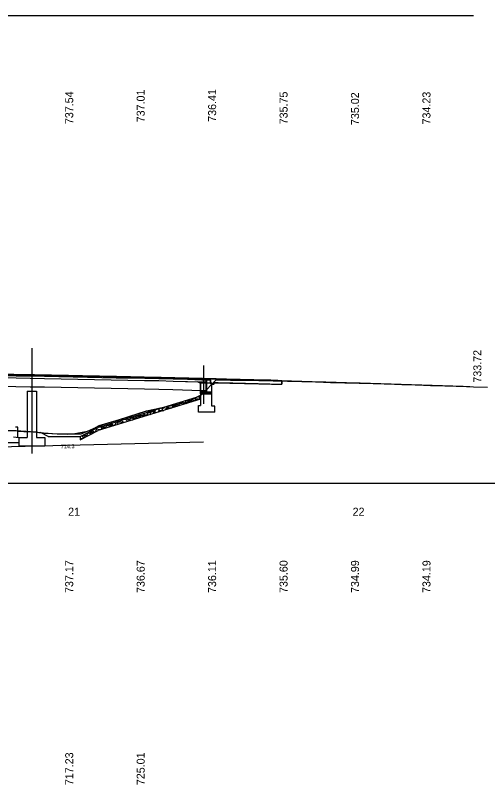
# Model space of a CAD drawing. Extents: x -434 to 1339, y -871 to 603.
# Drawn here: x 579.8 to 745, y -105.4 to 163.6 of the extents above; entities that cross this region are included whole.
import ezdxf

# ---------------------------------------------------------------- set-up
doc = ezdxf.new("R2010")
doc.units = 0
for name, color, linetype in [('BR_P_Brg_Pad_Object', 7, 'Continuous'), ('BR_P_Gen_Approach_Slab', 7, 'Continuous'), ('BR_P_Gen_Hatch', 7, 'Continuous'), ('BR_P_Gen_Slope_Protection', 7, 'Continuous'), ('BR_P_Slab_Object', 7, 'Continuous'), ('BR_P_Sub_Const_Joint', 7, 'Continuous'), ('BR_P_Sub_Object', 7, 'Continuous'), ('BR_X_Beam_Object', 7, 'Continuous'), ('BR_X_Gen_Approach_Slab', 7, 'Continuous'), ('BR_X_Sub_Centerline', 7, 'Continuous'), ('BR_X_Sub_Object', 7, 'Continuous'), ('Default', 7, 'Continuous'), ('GK_Cells', 7, 'Continuous'), ('PF_P_Grade_Line', 7, 'Continuous'), ('PF_P_Sta_Elev_Text', 7, 'Continuous'), ('PF_P_Text', 7, 'Continuous'), ('PF_X_Ground_Line', 7, 'Continuous'), ('SC_Scratch1', 7, 'Continuous'), ('SC_Scratch2', 7, 'Continuous'), ('XS_P_Annotation', 7, 'Continuous'), ('XS_P_Barrier_Surface', 7, 'Continuous'), ('XS_P_Ditch_Bottom', 7, 'Continuous'), ('XS_P_Finished_Grade', 7, 'Continuous'), ('XS_P_Finished_Grade_Seeded', 7, 'Continuous'), ('XS_P_Subgrade', 7, 'Continuous'), ('XS_X_Ground_Line', 7, 'Continuous')]:
    doc.layers.add(name, color=color, linetype=linetype)

msp = doc.modelspace()

# ---------------------------------------------------------------- linework, layer by layer
at = {"layer": 'BR_P_Brg_Pad_Object'}
msp.add_lwpolyline([(645.13, 31.83), (646.13, 31.83), (646.13, 31.66), (645.13, 31.66)], close=True, dxfattribs=at)
at = {"layer": 'BR_P_Gen_Approach_Slab'}
for p, q in [((649.03, 34.74), (649.46, 35.17)), ((673, 34.55), (673, 35.8)), ((649.03, 34.74), (648.53, 34.74))]:
    msp.add_line(p, q, dxfattribs=at)
msp.add_open_spline([(649.46, 35.17), (657.31, 34.97), (665.16, 34.77), (673, 34.55)], degree=2, dxfattribs=at)
at = {"layer": 'BR_P_Gen_Hatch'}
for p, q in [((643.57, 35.44), (644.57, 34.95)), ((649.03, 34.74), (649.46, 35.17)), ((673, 34.55), (673, 35.8)), ((644.57, 34.95), (644.57, 31.24)), ((648.53, 31.24), (648.53, 34.74)), ((648.53, 34.74), (649.03, 34.74)), ((644.57, 31.24), (648.53, 31.24))]:
    msp.add_line(p, q, dxfattribs=at)
for points in [[(355.72, 38.2), (400, 38.39), (405, 38.4), (410, 38.38), (450, 38.22), (454.99, 38.18), (494.99, 37.8), (499.99, 37.75), (534.99, 37.4), (539.99, 37.35), (579.99, 36.78), (584.99, 36.71), (589.99, 36.61), (624.99, 35.92), (629.98, 35.83), (634.98, 35.69), (643.57, 35.44)], [(642.45, 29.76), (642.47, 29.76), (642.76, 29.41), (642.72, 29.05), (642.39, 28.76), (642.1, 28.75), (641.81, 28.95)], [(643.27, 30.01), (642.95, 29.73), (642.66, 29.73), (642.57, 29.79)], [(644.45, 29.33), (644.27, 29.49), (644.17, 29.9), (644.21, 30.24)], [(644.21, 30.22), (644.25, 30.31)], [(634.3, 27.25), (634.38, 27.22), (634.69, 26.85), (634.7, 26.53), (634.42, 26.26), (633.86, 26.19), (633.29, 26.38), (632.92, 26.73), (632.91, 26.83)], [(636.05, 27.79), (636.05, 27.53), (635.77, 27.26), (635.21, 27.19), (634.67, 27.37)], [(635.02, 26.43), (634.99, 26.61), (635.28, 26.95), (635.73, 26.94), (635.92, 26.71)], [(636.06, 26.95), (636.01, 27.23), (636.19, 27.44), (636.46, 27.43), (636.63, 27.22), (636.61, 27.01), (636.45, 26.87)], [(636.32, 26.83), (636.23, 26.83), (636.06, 26.95)], [(637.39, 27.16), (637.14, 27.4), (637.08, 27.74), (637.34, 28.05), (637.76, 28.14), (638.1, 28.1)], [(638.07, 28.11), (638.59, 27.88), (638.83, 27.6)], [(638.5, 28.01), (638.42, 28.49), (638.45, 28.53)], [(639.21, 28.76), (639.45, 28.47), (639.42, 28.11), (639.08, 27.82), (638.8, 27.82), (638.5, 28.01)], [(639.42, 27.78), (639.52, 28.02), (639.89, 28.33), (640.21, 28.33), (640.44, 28.09)], [(640.19, 28.55), (640.14, 28.84), (640.32, 29.04), (640.59, 29.03), (640.76, 28.82), (640.74, 28.61), (640.54, 28.44), (640.36, 28.43), (640.19, 28.55)], [(640.61, 29.19), (640.6, 29.19), (640.59, 29.19)], [(640.75, 28.19), (640.71, 28.4), (641.01, 28.73), (641.46, 28.72), (641.67, 28.47)], [(641.81, 28.95), (641.72, 29.43), (641.85, 29.57)], [(643.06, 28.9), (643.02, 29.14), (643.32, 29.48), (643.77, 29.47), (644, 29.19)], [(624.67, 24.3), (624.55, 23.94), (624.2, 23.58), (623.85, 23.52), (623.55, 23.78), (623.51, 23.94)], [(625.05, 23.92), (624.97, 24.39)], [(625.79, 24.64), (626, 24.38), (625.97, 24.02), (625.63, 23.73), (625.34, 23.73), (625.05, 23.92)], [(627.23, 25.09), (627.24, 24.97), (626.96, 24.7), (626.4, 24.63), (626.09, 24.73)], [(626.86, 23.93), (626.9, 24.24)], [(626.89, 24.21), (627.11, 24.73), (627.48, 25.04), (627.8, 25.05), (628.07, 24.77), (628.13, 24.31)], [(627.94, 25.09), (627.91, 25.29)], [(628.44, 25.45), (628.51, 25.36), (628.49, 25.15), (628.29, 24.97), (628.12, 24.97), (627.94, 25.09)], [(628.86, 24.54), (628.73, 24.66), (628.64, 25.07), (628.68, 25.41)], [(628.67, 25.39), (628.74, 25.55)], [(629.86, 25.89), (629.92, 25.38), (629.73, 24.81), (629.72, 24.8)], [(630.18, 25.48), (630.1, 25.96), (630.11, 25.97)], [(630.9, 26.21), (631.13, 25.93), (631.1, 25.57), (630.76, 25.28), (630.47, 25.28), (630.18, 25.48)], [(631.08, 25.22), (631.17, 25.32), (631.58, 25.41), (631.67, 25.4)], [(632.06, 26.57), (632.04, 26.53), (631.69, 26.16), (631.35, 26.1), (631.14, 26.28)], [(632.5, 25.66), (632.45, 25.94), (632.75, 26.27), (633.19, 26.26), (633.45, 25.95)], [(617.96, 21.19), (617.89, 21.18), (617.33, 21.37), (616.96, 21.73), (616.93, 21.92)], [(618.19, 22.31), (618.42, 22.21), (618.73, 21.84), (618.74, 21.52), (618.59, 21.39)], [(619.05, 22.29), (619.01, 22.56)], [(619.93, 22.84), (620, 22.75), (619.97, 22.39), (619.64, 22.1), (619.35, 22.1), (619.06, 22.29)], [(619.77, 21.75), (620.03, 22.04), (620.45, 22.14), (620.78, 22.1)], [(620.17, 22.85), (620.16, 22.91)], [(621.11, 23.21), (621.09, 22.95), (620.75, 22.66), (620.46, 22.65), (620.17, 22.85)], [(620.76, 22.1), (620.83, 22.07)], [(621.16, 22.17), (621.1, 22.49), (621.4, 22.83), (621.85, 22.82), (622.13, 22.47)], [(622.83, 23.73), (622.74, 23.45), (622.39, 23.09), (622.04, 23.03), (621.74, 23.3), (621.72, 23.39)], [(622.85, 22.69), (622.82, 22.84), (623, 23.04), (623.27, 23.03), (623.41, 22.86)], [(622.94, 23.3), (622.89, 23.59), (623.07, 23.79), (623.33, 23.78), (623.51, 23.57), (623.49, 23.36), (623.29, 23.18), (623.11, 23.18), (622.94, 23.3)], [(624.45, 23.18), (624.41, 23.43), (624.7, 23.76), (625.15, 23.76), (625.38, 23.47)], [(607.98, 19.1), (608.04, 18.91), (607.95, 18.31), (607.67, 17.9), (607.34, 17.78), (606.99, 17.99), (606.83, 18.39), (606.82, 18.52)], [(609.57, 19.66), (609.6, 19.65), (609.91, 19.28), (609.92, 18.97), (609.64, 18.69), (609.08, 18.63), (608.51, 18.82), (608.14, 19.18)], [(609.78, 18.68), (609.8, 18.73), (610.17, 19.04), (610.48, 19.05), (610.6, 18.93)], [(610.72, 20.01), (610.7, 19.84), (610.37, 19.55), (610.08, 19.55), (609.8, 19.73)], [(610.62, 19.09), (610.57, 19.37), (610.75, 19.57), (611.02, 19.57), (611.19, 19.36), (611.18, 19.14), (611.11, 19.09)], [(610.77, 18.99), (610.62, 19.09)], [(611.33, 19.16), (611.36, 19.41)], [(611.36, 19.38), (611.58, 19.9), (611.95, 20.21), (612.26, 20.22), (612.54, 19.94), (612.58, 19.54)], [(613.42, 20.85), (613.41, 20.69), (613.07, 20.4), (612.79, 20.4), (612.53, 20.57)], [(612.84, 19.62), (612.78, 19.95), (613.08, 20.29), (613.53, 20.28), (613.82, 19.93), (613.81, 19.92)], [(614.89, 21.3), (614.92, 21.09), (614.73, 20.52), (614.38, 20.16), (614.03, 20.1), (613.73, 20.37), (613.64, 20.78), (613.65, 20.91)], [(615.81, 20.53), (615.61, 20.73), (615.55, 21.08), (615.82, 21.38), (616.23, 21.47), (616.57, 21.43)], [(616.55, 21.44), (617.06, 21.21), (617.26, 20.98)], [(603.02, 16.6), (603.05, 16.59), (603.42, 16.28), (603.48, 15.97), (603.25, 15.65), (602.71, 15.49), (602.38, 15.54)], [(604.09, 17.14), (604.1, 16.96), (603.82, 16.62), (603.53, 16.57), (603.23, 16.71)], [(603.38, 15.66), (603.4, 15.71), (603.71, 16.08), (604.02, 16.14), (604.15, 16.05)], [(604.15, 16.21), (604.05, 16.48), (604.2, 16.71), (604.46, 16.75), (604.67, 16.57), (604.68, 16.36), (604.63, 16.29)], [(604.31, 16.13), (604.15, 16.21)], [(604.82, 16.62), (604.95, 17.17), (605.27, 17.54), (605.58, 17.6), (605.89, 17.37), (606, 16.98)], [(604.84, 16.4), (604.82, 16.65)], [(606.61, 18.41), (606.62, 18.26), (606.34, 17.91), (606.06, 17.86), (605.77, 17.99)], [(606.24, 17.11), (606.13, 17.43), (606.37, 17.8), (606.81, 17.87), (607.15, 17.57), (607.15, 17.57)]]:
    msp.add_lwpolyline(points, dxfattribs=at)
msp.add_spline([(673, 35.8), (672.8, 35.81), (663.2, 36.07), (653.6, 36.32), (644, 36.56), (634.4, 36.79), (624.8, 37.01), (615.2, 37.23), (605.6, 37.43), (596, 37.62), (586.4, 37.81), (576.8, 37.98), (567.2, 38.15), (557.6, 38.3), (548, 38.45), (538.4, 38.59), (528.8, 38.72), (519.2, 38.83), (509.6, 38.94), (500, 39.04), (490.4, 39.13), (480.8, 39.21), (471.2, 39.28), (461.6, 39.34), (452, 39.4), (442.4, 39.44), (432.8, 39.47), (423.2, 39.5), (413.6, 39.51), (404, 39.51), (394.4, 39.51), (384.8, 39.5), (375.2, 39.47), (365.6, 39.44), (356, 39.4), (346.4, 39.34), (336.8, 39.28), (327.2, 39.21), (326.42, 39.2)], degree=3, dxfattribs=at)
msp.add_open_spline([(649.46, 35.17), (657.31, 34.97), (665.16, 34.77), (673, 34.55)], degree=2, dxfattribs=at)
at = {"layer": 'BR_P_Gen_Slope_Protection'}
for p, q in [((644.57, 30.41), (608.36, 19.29)), ((644.57, 29.36), (608.74, 18.36)), ((602.38, 16.3), (608.36, 19.29)), ((602.38, 15.18), (608.74, 18.36)), ((602.38, 16.3), (602.38, 15.18))]:
    msp.add_line(p, q, dxfattribs=at)
at = {"layer": 'BR_P_Slab_Object'}
msp.add_lwpolyline([(355.72, 38.2), (400, 38.39), (405, 38.4), (410, 38.38), (450, 38.22), (454.99, 38.18), (494.99, 37.8), (499.99, 37.75), (534.99, 37.4), (539.99, 37.35), (579.99, 36.78), (584.99, 36.71), (589.99, 36.61), (624.99, 35.92), (629.98, 35.83), (634.98, 35.69), (643.57, 35.44)], dxfattribs=at)
at = {"layer": 'BR_P_Sub_Const_Joint'}
msp.add_line((648, 34.95), (644.57, 34.95), dxfattribs=at)
at = {"layer": 'BR_P_Sub_Object'}
for p, q in [((644.57, 34.95), (643.57, 35.44)), ((648, 34.95), (648, 36.46)), ((644.57, 31.83), (644.57, 34.95)), ((648.53, 34.95), (648, 34.95)), ((648.53, 31.83), (648.53, 34.95)), ((648.53, 31.83), (644.57, 31.83)), ((648.53, 31.66), (644.57, 31.66)), ((644.57, 31.24), (644.57, 31.66)), ((648.53, 31.24), (644.57, 31.24)), ((648.53, 31.24), (648.53, 31.66))]:
    msp.add_line(p, q, dxfattribs=at)
at = {"layer": 'BR_X_Beam_Object'}
for points in [[(352.99, 38.18), (355, 38.19), (400, 38.39), (405, 38.4), (410, 38.38), (450, 38.22), (454.99, 38.18), (494.99, 37.8), (499.99, 37.75), (534.99, 37.4), (539.99, 37.35), (579.99, 36.78), (584.99, 36.71), (589.99, 36.61), (624.99, 35.92), (629.98, 35.83), (634.98, 35.69), (644.98, 35.4), (646.43, 35.36)], [(352.99, 35.18), (355.02, 35.19), (400.01, 35.39), (405, 35.4), (409.98, 35.38), (449.98, 35.22), (454.97, 35.18), (494.96, 34.8), (499.96, 34.75), (534.96, 34.4), (539.96, 34.35), (579.95, 33.78), (584.94, 33.71), (589.93, 33.61), (624.93, 32.92), (629.91, 32.83), (634.89, 32.69), (644.89, 32.41), (646.43, 32.36)]]:
    msp.add_lwpolyline(points, dxfattribs=at)
at = {"layer": 'BR_X_Gen_Approach_Slab'}
for p, q in [((649.03, 34.49), (649.58, 35.04)), ((673, 35.65), (673, 34.56)), ((649.03, 34.49), (648.53, 34.49))]:
    msp.add_line(p, q, dxfattribs=at)
msp.add_lwpolyline([(649.58, 35.04), (659.98, 34.88), (664.97, 34.76), (673, 34.56)], dxfattribs=at)
at = {"layer": 'BR_X_Sub_Centerline'}
for p, q in [((585.53, 47.14), (585.53, 10.4)), ((645.63, 41.18), (645.63, 27.68))]:
    msp.add_line(p, q, dxfattribs=at)
at = {"layer": 'BR_X_Sub_Object'}
for p, q in [((646.43, 36.11), (646.43, 32.36)), ((648, 36.03), (646.68, 36.03)), ((646.68, 36.03), (646.68, 31.41)), ((648, 36.03), (648, 34.7)), ((648.53, 34.7), (648, 34.7)), ((648.53, 26.85), (648.53, 34.7)), ((583.94, 32.17), (583.94, 16)), ((583.94, 32.17), (587.11, 32.17)), ((587.11, 32.17), (587.11, 16)), ((646.68, 31.41), (644.57, 31.41)), ((644.57, 31.41), (644.57, 27.1)), ((643.78, 24.85), (643.78, 27.1)), ((643.78, 27.1), (644.57, 27.1)), ((649.53, 24.85), (643.78, 24.85)), ((649.53, 26.85), (648.53, 26.85)), ((649.53, 24.85), (649.53, 26.85)), ((580.94, 16), (580.94, 13)), ((580.94, 16), (583.94, 16)), ((587.11, 16), (590.11, 16)), ((590.11, 16), (590.11, 13)), ((580.94, 13), (590.11, 13))]:
    msp.add_line(p, q, dxfattribs=at)
at = {"layer": 'Default'}
msp.add_line((0, 0), (1050.49, 0), dxfattribs=at)
at = {"layer": 'GK_Cells'}
msp.add_line((0, 0), (1000, 0), dxfattribs=at)
at = {"layer": 'PF_P_Grade_Line'}
msp.add_spline([(260, 38.45), (269.6, 38.59), (279.2, 38.71), (288.8, 38.83), (298.4, 38.94), (308, 39.04), (317.6, 39.13), (327.2, 39.21), (336.8, 39.28), (346.4, 39.34), (356, 39.4), (365.6, 39.44), (375.2, 39.47), (384.8, 39.5), (394.4, 39.51), (404, 39.51), (413.6, 39.51), (423.2, 39.5), (432.8, 39.47), (442.4, 39.44), (452, 39.4), (461.6, 39.34), (471.2, 39.28), (480.8, 39.21), (490.4, 39.13), (500, 39.04), (509.6, 38.94), (519.2, 38.83), (528.8, 38.72), (538.4, 38.59), (548, 38.45), (557.6, 38.3), (567.2, 38.15), (576.8, 37.98), (586.4, 37.81), (596, 37.62), (605.6, 37.43), (615.2, 37.23), (624.8, 37.01), (634.4, 36.79), (644, 36.56), (653.6, 36.32), (663.2, 36.07), (672.8, 35.81), (682.4, 35.54), (692, 35.26), (701.6, 34.97), (711.2, 34.67), (720.8, 34.36), (730.4, 34.05), (740, 33.72)], degree=3, dxfattribs=at)
at = {"layer": 'PF_P_Text'}
msp.add_line((260, 163.55), (740, 163.55), dxfattribs=at)
at = {"layer": 'PF_X_Ground_Line'}
msp.add_lwpolyline([(575, 37.6), (580, 37.53), (585, 37.46), (590, 37.36), (595, 37.27), (600, 37.17), (605, 37.07), (610, 36.97), (615, 36.87), (620, 36.77), (625, 36.67), (630, 36.58), (635, 36.44), (640, 36.3), (645, 36.15), (647, 36.1)], dxfattribs=at)
at = {"layer": 'SC_Scratch1'}
msp.add_line((499.7, 11), (645.63, 14.4), dxfattribs=at)
at = {"layer": 'SC_Scratch2'}
msp.add_lwpolyline([(575, 18.45), (580, 18.37), (585, 18.01), (590, 17.52), (595, 17.25), (600, 17.23), (605, 18.2), (610, 20.39), (615, 21.84), (620, 23.41), (625, 25.01), (630, 26.19), (635, 27.29), (640, 28.39), (645, 30.93), (650, 36.11), (655, 36.04), (660, 35.96), (665, 35.84), (670, 35.72), (675, 35.6), (680, 35.48), (685, 35.36), (690, 35.23), (695, 35.11), (700, 34.99), (705, 34.83), (710, 34.67), (715, 34.51), (720, 34.35), (725, 34.19), (730, 34.03), (735, 33.87), (740, 33.71), (745, 33.56)], dxfattribs=at)
at = {"layer": 'XS_P_Barrier_Surface'}
for p, q in [((580.62, 19.57), (579.76, 19.57)), ((580.62, 19.57), (579.87, 19.57)), ((580.62, 19.57), (580.66, 19.53)), ((580.66, 16.03), (580.66, 19.53))]:
    msp.add_line(p, q, dxfattribs=at)
at = {"layer": 'XS_P_Ditch_Bottom'}
msp.add_line((591.28, 16.3), (602.38, 16.3), dxfattribs=at)
at = {"layer": 'XS_P_Finished_Grade'}
for p, q in [((591.28, 16.3), (588.52, 17.68)), ((580.99, 16), (581.71, 15.95))]:
    msp.add_line(p, q, dxfattribs=at)
at = {"layer": 'XS_P_Finished_Grade_Seeded'}
msp.add_line((579.06, 16.15), (580.99, 16), dxfattribs=at)
at = {"layer": 'XS_P_Subgrade'}
for p in [(502.51, 13.8), (580.99, 16)]:
    msp.add_line(p, (580.99, 14.2), dxfattribs=at)
at = {"layer": 'XS_X_Ground_Line'}
for p, q in [((615.84, 22.09), (622.78, 24.33)), ((622.78, 24.33), (625.65, 25.24)), ((625.65, 25.24), (630.07, 26.22)), ((612.18, 21.06), (615.84, 22.09)), ((602.76, 17.25), (607.22, 19.12)), ((607.22, 19.12), (609.05, 20.11)), ((609.05, 20.11), (612.18, 21.06)), ((580.66, 18.21), (582.71, 18.08)), ((582.71, 18.08), (586.91, 17.9)), ((586.91, 17.9), (587.64, 17.8)), ((587.64, 17.8), (589.65, 17.53)), ((589.65, 17.53), (594.35, 17.23)), ((594.35, 17.23), (596.07, 17.2)), ((596.07, 17.2), (597.98, 17.1)), ((597.98, 17.1), (599.19, 17.18)), ((599.19, 17.18), (602.76, 17.25))]:
    msp.add_line(p, q, dxfattribs=at)
msp.add_lwpolyline([(630.07, 26.22), (635, 27.29), (640, 28.39), (645, 30.93), (650, 36.11), (655, 36.04), (660, 35.96), (665, 35.84), (670, 35.72), (675, 35.6), (680, 35.48), (685, 35.36), (690, 35.23), (695, 35.11), (700, 34.99), (705, 34.83), (710, 34.67), (715, 34.51), (720, 34.35), (725, 34.19), (730, 34.03), (735, 33.87), (740, 33.71), (745, 33.56)], dxfattribs=at)

# ---------------------------------------------------------------- texts
at = {"layer": 'Default'}
for s, p in [('737.17', (600, -38.43)), ('736.67', (625, -38.43)), ('736.11', (650, -38.43)), ('735.60', (675, -38.43)), ('734.99', (700, -38.43)), ('734.19', (725, -38.43)), ('717.23', (600, -105.62)), ('725.01', (625, -105.62))]:
    msp.add_text(s, height=2.8, rotation=90, dxfattribs=at).set_placement(p)
at = {"layer": 'PF_P_Sta_Elev_Text'}
for s, p in [('21', (598.23, -11.4)), ('21', (598.23, -11.4)), ('22', (697.76, -11.4))]:
    msp.add_text(s, height=2.8, dxfattribs=at).set_placement(p)
at = {"layer": 'PF_P_Text'}
for s, p in [('737.01', (625, 126.16)), ('736.41', (650, 126.32)), ('737.54', (600, 125.52)), ('735.75', (675, 125.45)), ('735.02', (700, 125.19)), ('734.23', (725, 125.41)), ('733.72', (742.8, 35.12))]:
    msp.add_text(s, height=2.8, rotation=90, dxfattribs=at).set_placement(p)
at = {"layer": 'XS_P_Annotation'}
msp.add_text('714.3', height=1.4, dxfattribs=at).set_placement((595.62, 12.2))

doc.saveas('drawing.dxf')
